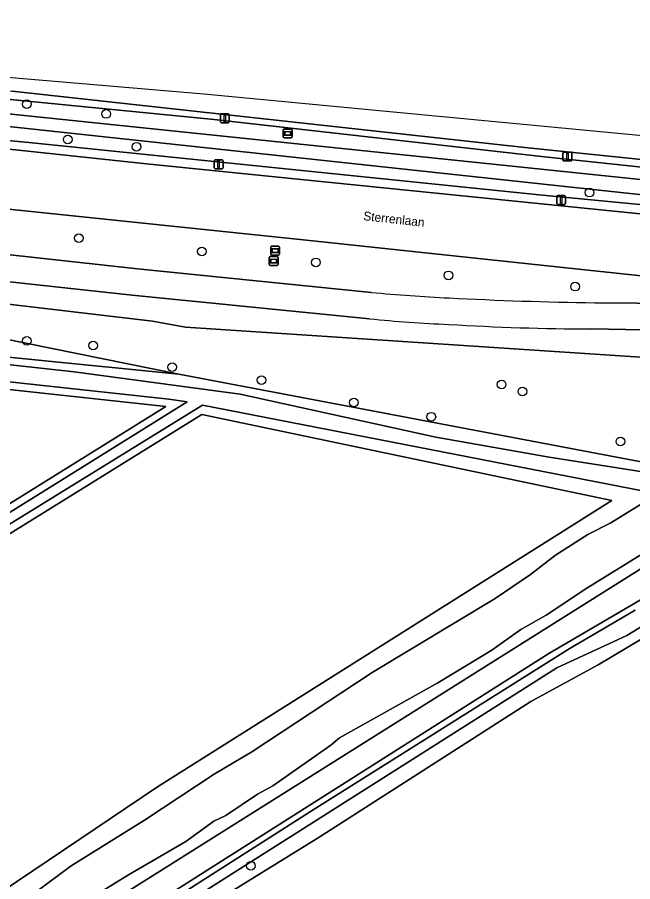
# Model space of a CAD drawing. Extents: x 162788 to 163838, y 385791 to 386523.
# Drawn here: x 163529.6 to 163598.9, y 386420.1 to 386517.4 of the extents above; entities that cross this region are included whole.
import ezdxf

# ---------------------------------------------------------------- set-up
doc = ezdxf.new("R2010")
doc.units = 0
for name, color, linetype in [('IMGEO_Berm_groen', 7, 'Continuous'), ('IMGEO_Boom', 7, 'Continuous'), ('IMGEO_Fietspad_gesloten', 7, 'Continuous'), ('IMGEO_Grasland_overig', 7, 'Continuous'), ('IMGEO_Groenvoorziening', 7, 'Continuous'), ('IMGEO_Informatiebord', 7, 'Continuous'), ('IMGEO_Lichtmast', 7, 'Continuous'), ('IMGEO_Loofbos', 7, 'Continuous'), ('IMGEO_Oever', 7, 'Continuous'), ('IMGEO_Openbare_ruimte_label', 7, 'Continuous'), ('IMGEO_OVBaan_gesloten', 7, 'Continuous'), ('IMGEO_Rijbaan_regionaal_gesloten', 7, 'Continuous'), ('IMGEO_Waterloop', 7, 'Continuous')]:
    doc.layers.add(name, color=color, linetype=linetype)

msp = doc.modelspace()

# ---------------------------------------------------------------- linework, layer by layer
at = {"layer": 'IMGEO_Berm_groen'}
for points in [[(163502.268, 386510.765), (163511.024, 386509.903), (163513.566, 386509.634), (163551.797, 386505.898)], [(163488.349, 386506.668), (163510.404, 386504.494), (163544.171, 386500.892), (163632.748, 386491.925), (163633.433, 386497.926), (163586.787, 386502.74), (163529.046, 386509.095)], [(163614.95, 386494.842), (163588.401, 386497.397), (163531.293, 386503.262), (163504.256, 386505.867)], [(163551.797, 386505.898), (163588.967, 386501.7), (163615.146, 386498.908)], [(163408.845, 386505.184), (163382.823, 386504.918), (163339.084, 386504.348), (163313.816, 386504.019), (163312.779, 386502.838), (163322.556, 386503.048), (163336.698, 386502.829), (163341.58, 386502.733), (163354.063, 386502.487), (163377.597, 386501.753), (163392.717, 386501.21), (163422.157, 386499.862), (163437.07, 386498.936), (163447.684, 386498.2), (163451.775, 386497.917), (163476.422, 386495.841), (163497.382, 386493.95), (163513.463, 386492.329), (163543.158, 386489.078), (163569.498, 386486.424)], [(163594.648, 386485.25), (163604.116, 386485.157), (163620.131, 386484.654), (163620.331, 386486.107), (163561.492, 386492.38), (163515.306, 386497.176)]]:
    msp.add_lwpolyline(points, dxfattribs=at)
for centre, radius, start, end in [((163587.435, 386675.239), 189.666, 264.57336, 267.22094), ((163602.356, 386962.857), 477.67, 267.10602, 269.07544)]:
    msp.add_arc(centre, radius, start, end, dxfattribs=at)
at = {"layer": 'IMGEO_Boom'}
for centre in [(163530.718, 386507.626), (163539.654, 386506.521), (163535.311, 386503.647), (163543.051, 386502.827), (163594.045, 386497.66), (163536.575, 386492.528), (163550.405, 386491.033), (163563.257, 386489.802), (163578.166, 386488.336), (163592.423, 386487.075), (163530.721, 386480.963), (163538.188, 386480.452), (163547.076, 386477.997), (163557.126, 386476.527), (163584.159, 386476.045), (163586.495, 386475.27), (163567.51, 386474.032), (163576.244, 386472.422), (163597.527, 386469.639), (163555.927, 386421.855)]:
    msp.add_circle(centre, 0.489, dxfattribs=at)
at = {"layer": 'IMGEO_Fietspad_gesloten'}
for points in [[(163476.422, 386495.841), (163451.775, 386497.917), (163447.684, 386498.2), (163447.558, 386495.135), (163476.013, 386493.062), (163496.644, 386491.109), (163542.581, 386486.123), (163569.285, 386483.446)], [(163569.498, 386486.424), (163543.158, 386489.078), (163513.463, 386492.329), (163497.382, 386493.95), (163476.422, 386495.841)], [(163620.346, 386481.447), (163637.893, 386479.866), (163646.607, 386478.939), (163644.408, 386482.109), (163620.131, 386484.654), (163604.116, 386485.157), (163594.648, 386485.25)], [(163594.227, 386482.314), (163603.992, 386482.133)]]:
    msp.add_lwpolyline(points, dxfattribs=at)
for centre, radius, start, end in [((163587.435, 386675.239), 189.666, 264.57336, 267.22094), ((163602.356, 386962.857), 477.67, 267.10602, 269.07544), ((163583.998, 386629.849), 147.141, 264.2612, 267.74985), ((163594.835, 386753.88), 271.567, 266.49257, 269.87174)]:
    msp.add_arc(centre, radius, start, end, dxfattribs=at)
at = {"layer": 'IMGEO_Grasland_overig'}
for points in [[(163609.972, 386461.674), (163530.606, 386411.736), (163508.344, 386398.609), (163502.97, 386394.804), (163500.738, 386394.072), (163499.305, 386392.84), (163498.074, 386392.291), (163497.125, 386391.868), (163496.628, 386391.81), (163494.388, 386391.549), (163468.576, 386408.683), (163466.904, 386409.785), (163463.499, 386412.323), (163460.871, 386414.287), (163452.188, 386431.166), (163452.353, 386431.82), (163452.585, 386432.415), (163452.967, 386432.905), (163451.764, 386435.791), (163426.74, 386484.123)], [(163689.349, 386265.559), (163554.317, 386352.369), (163530.224, 386368.614), (163500.811, 386388.481), (163501.915, 386389.741), (163502.813, 386390.765), (163508.757, 386394.537), (163589.476, 386445.759), (163600.071, 386451.949)]]:
    msp.add_lwpolyline(points, dxfattribs=at)
at = {"layer": 'IMGEO_Groenvoorziening'}
for points in [[(163496.644, 386491.109), (163476.013, 386493.062), (163447.558, 386495.135), (163436.207, 386495.962), (163421.921, 386496.877), (163416.565, 386497.119), (163416.729, 386495.064), (163447.481, 386493.27), (163467.054, 386491.699), (163487.006, 386489.37), (163500, 386488.248), (163507.278, 386487.619), (163544.863, 386483.183), (163548.582, 386482.522), (163613.437, 386478.233), (163623.373, 386477.329), (163632.55, 386476.266), (163639.446, 386472.523), (163647.005, 386478.019), (163647.317, 386477.986), (163646.607, 386478.939), (163637.893, 386479.866), (163620.346, 386481.447)], [(163613.437, 386478.233), (163548.582, 386482.522), (163544.863, 386483.183), (163507.278, 386487.619), (163500, 386488.248), (163487.006, 386489.37), (163467.054, 386491.699), (163447.481, 386493.27), (163416.729, 386495.064), (163416.941, 386492.397), (163430.626, 386491.16), (163447.119, 386489.171), (163500, 386483.982), (163527.829, 386481.252), (163547.829, 386477.218), (163603.437, 386466.663)], [(163569.285, 386483.446), (163542.581, 386486.123), (163496.644, 386491.109)], [(163603.992, 386482.133), (163594.227, 386482.314)]]:
    msp.add_lwpolyline(points, dxfattribs=at)
msp.add_lwpolyline([(163447.119, 386489.171), (163430.626, 386491.16), (163416.941, 386492.397), (163417.443, 386489.736), (163418.278, 386486.121), (163420.488, 386485.85), (163420.359, 386486.513), (163420.518, 386487.534), (163420.904, 386488.099), (163421.598, 386488.641), (163422.419, 386489.101), (163429.924, 386488.142), (163446.859, 386486.473), (163471.729, 386483.62), (163478.327, 386483.016), (163500, 386481.984), (163547.829, 386477.218), (163527.829, 386481.252), (163500, 386483.982)], close=True, dxfattribs=at)
for centre, radius, start, end in [((163583.998, 386629.849), 147.141, 264.2612, 267.74985), ((163594.835, 386753.88), 271.567, 266.49257, 269.87174)]:
    msp.add_arc(centre, radius, start, end, dxfattribs=at)
at = {"layer": 'IMGEO_Informatiebord'}
for p, q in [((163559.582, 386503.922), (163559.582, 386504.722)), ((163559.582, 386504.722), (163559.582, 386503.922)), ((163559.682, 386504.822), (163560.472, 386504.822)), ((163560.472, 386504.822), (163559.682, 386504.822)), ((163560.572, 386504.722), (163560.572, 386503.922)), ((163560.572, 386503.922), (163560.572, 386504.722)), ((163560.472, 386503.822), (163559.682, 386503.822)), ((163559.682, 386503.822), (163560.472, 386503.822)), ((163558.163, 386490.727), (163558.163, 386491.527)), ((163558.163, 386491.527), (163558.163, 386490.727)), ((163558.263, 386491.627), (163559.053, 386491.627)), ((163559.053, 386491.627), (163558.263, 386491.627)), ((163559.153, 386491.527), (163559.153, 386490.727)), ((163559.153, 386490.727), (163559.153, 386491.527)), ((163557.997, 386489.548), (163557.997, 386490.348)), ((163557.997, 386490.348), (163557.997, 386489.548)), ((163558.097, 386490.448), (163558.887, 386490.448)), ((163558.887, 386490.448), (163558.097, 386490.448)), ((163559.053, 386490.627), (163558.263, 386490.627)), ((163558.263, 386490.627), (163559.053, 386490.627)), ((163558.987, 386490.348), (163558.987, 386489.548)), ((163558.987, 386489.548), (163558.987, 386490.348)), ((163558.887, 386489.448), (163558.097, 386489.448)), ((163558.097, 386489.448), (163558.887, 386489.448))]:
    msp.add_line(p, q, dxfattribs=at)
for points in [[(163559.683, 386504.554), (163560.471, 386504.554), (163560.471, 386504.09), (163559.683, 386504.09), (163559.683, 386504.554)], [(163559.748, 386504.489), (163559.748, 386504.155), (163560.406, 386504.155), (163560.406, 386504.489), (163559.748, 386504.489)], [(163558.264, 386491.359), (163559.052, 386491.359), (163559.052, 386490.895), (163558.264, 386490.895), (163558.264, 386491.359)], [(163558.329, 386491.294), (163558.329, 386490.96), (163558.987, 386490.96), (163558.987, 386491.294), (163558.329, 386491.294)], [(163558.098, 386490.18), (163558.886, 386490.18), (163558.886, 386489.716), (163558.098, 386489.716), (163558.098, 386490.18)], [(163558.163, 386490.115), (163558.163, 386489.781), (163558.821, 386489.781), (163558.821, 386490.115), (163558.163, 386490.115)]]:
    msp.add_lwpolyline(points, dxfattribs=at)
for centre, start, end in [((163559.682, 386504.722), 90, 180), ((163559.682, 386504.722), 90, 180), ((163560.472, 386504.722), 0, 90), ((163560.472, 386504.722), 360, 90), ((163559.682, 386503.922), 180, 270), ((163559.682, 386503.922), 180, 270), ((163560.472, 386503.922), 270, 0), ((163560.472, 386503.922), 270, 0), ((163558.263, 386491.527), 90, 180), ((163558.263, 386491.527), 90, 180), ((163559.053, 386491.527), 0, 90), ((163559.053, 386491.527), 360, 90), ((163558.097, 386490.348), 90, 180), ((163558.097, 386490.348), 90, 180), ((163558.263, 386490.727), 180, 270), ((163558.263, 386490.727), 180, 270), ((163558.887, 386490.348), 0, 90), ((163558.887, 386490.348), 360, 90), ((163559.053, 386490.727), 270, 0), ((163559.053, 386490.727), 270, 0), ((163558.097, 386489.548), 180, 270), ((163558.097, 386489.548), 180, 270), ((163558.887, 386489.548), 270, 0), ((163558.887, 386489.548), 270, 0)]:
    msp.add_arc(centre, 0.1, start, end, dxfattribs=at)
at = {"layer": 'IMGEO_Lichtmast'}
for p, q in [((163552.505, 386505.618), (163552.505, 386506.418)), ((163552.505, 386506.418), (163552.505, 386505.618)), ((163552.605, 386506.518), (163553.395, 386506.518)), ((163553.395, 386506.518), (163552.605, 386506.518)), ((163553.495, 386506.418), (163553.495, 386505.618)), ((163553.495, 386505.618), (163553.495, 386506.418)), ((163553.395, 386505.518), (163552.605, 386505.518)), ((163552.605, 386505.518), (163553.395, 386505.518)), ((163591.064, 386501.327), (163591.064, 386502.127)), ((163591.064, 386502.127), (163591.064, 386501.327)), ((163591.164, 386502.227), (163591.954, 386502.227)), ((163591.954, 386502.227), (163591.164, 386502.227)), ((163592.054, 386502.127), (163592.054, 386501.327)), ((163592.054, 386501.327), (163592.054, 386502.127)), ((163551.803, 386500.446), (163551.803, 386501.246)), ((163551.803, 386501.246), (163551.803, 386500.446)), ((163551.903, 386501.346), (163552.693, 386501.346)), ((163552.693, 386501.346), (163551.903, 386501.346)), ((163552.793, 386501.246), (163552.793, 386500.446)), ((163552.793, 386500.446), (163552.793, 386501.246)), ((163591.954, 386501.227), (163591.164, 386501.227)), ((163591.164, 386501.227), (163591.954, 386501.227)), ((163552.693, 386500.346), (163551.903, 386500.346)), ((163551.903, 386500.346), (163552.693, 386500.346)), ((163590.362, 386496.431), (163590.362, 386497.231)), ((163590.362, 386497.231), (163590.362, 386496.431)), ((163590.462, 386497.331), (163591.252, 386497.331)), ((163591.252, 386497.331), (163590.462, 386497.331)), ((163591.352, 386497.231), (163591.352, 386496.431)), ((163591.352, 386496.431), (163591.352, 386497.231)), ((163591.252, 386496.331), (163590.462, 386496.331)), ((163590.462, 386496.331), (163591.252, 386496.331))]:
    msp.add_line(p, q, dxfattribs=at)
for points in [[(163552.925, 386506.393), (163553.075, 386506.393), (163553.075, 386505.643), (163552.925, 386505.643), (163552.925, 386506.393)], [(163591.484, 386502.102), (163591.634, 386502.102), (163591.634, 386501.352), (163591.484, 386501.352), (163591.484, 386502.102)], [(163552.223, 386501.221), (163552.373, 386501.221), (163552.373, 386500.471), (163552.223, 386500.471), (163552.223, 386501.221)], [(163590.782, 386497.206), (163590.932, 386497.206), (163590.932, 386496.456), (163590.782, 386496.456), (163590.782, 386497.206)]]:
    msp.add_lwpolyline(points, dxfattribs=at)
for centre, start, end in [((163552.605, 386506.418), 90, 180), ((163552.605, 386506.418), 90, 180), ((163553.395, 386506.418), 0, 90), ((163553.395, 386506.418), 360, 90), ((163552.605, 386505.618), 180, 270), ((163552.605, 386505.618), 180, 270), ((163553.395, 386505.618), 270, 0), ((163553.395, 386505.618), 270, 0), ((163591.164, 386502.127), 90, 180), ((163591.164, 386502.127), 90, 180), ((163591.954, 386502.127), 0, 90), ((163591.954, 386502.127), 360, 90), ((163551.903, 386501.246), 90, 180), ((163551.903, 386501.246), 90, 180), ((163552.693, 386501.246), 0, 90), ((163552.693, 386501.246), 360, 90), ((163591.164, 386501.327), 180, 270), ((163591.164, 386501.327), 180, 270), ((163591.954, 386501.327), 270, 0), ((163591.954, 386501.327), 270, 0), ((163551.903, 386500.446), 180, 270), ((163551.903, 386500.446), 180, 270), ((163552.693, 386500.446), 270, 0), ((163552.693, 386500.446), 270, 0), ((163590.462, 386497.231), 90, 180), ((163590.462, 386497.231), 90, 180), ((163591.252, 386497.231), 0, 90), ((163591.252, 386497.231), 360, 90), ((163590.462, 386496.431), 180, 270), ((163590.462, 386496.431), 180, 270), ((163591.252, 386496.431), 270, 0), ((163591.252, 386496.431), 270, 0)]:
    msp.add_arc(centre, 0.1, start, end, dxfattribs=at)
at = {"layer": 'IMGEO_Loofbos'}
for points in [[(163426.74, 386484.123), (163451.764, 386435.791), (163452.967, 386432.905), (163453.493, 386433.2), (163454.277, 386433.331), (163454.763, 386433.281), (163455.373, 386433.133), (163460.662, 386422.733), (163462.288, 386420.222), (163499.058, 386443.123), (163499.013, 386443.525), (163499.213, 386444.012), (163499.548, 386444.436), (163546.342, 386473.582), (163499.936, 386478.596), (163470.849, 386479.85), (163459.326, 386482.058), (163429.606, 386483.871), (163427.714, 386484.103)], [(163501.293, 386442.202), (163500.215, 386442.074), (163499.665, 386442.243), (163499.333, 386442.544), (163499.068, 386443.031), (163499.058, 386443.123), (163462.288, 386420.222), (163465.159, 386415.79), (163493.758, 386397.39), (163494.965, 386396.918), (163496.171, 386397.548), (163545.437, 386430.752), (163596.56, 386462.976), (163550.418, 386472.656)], [(163652.297, 386455.08), (163652.01, 386454.984), (163642, 386454.381), (163641.895, 386453.88), (163641.744, 386453.509), (163641.406, 386452.947), (163635.326, 386451.747), (163618.327, 386454.372), (163612.285, 386454.746), (163595.027, 386444.488), (163587.439, 386440.362), (163563.524, 386425.009), (163514.155, 386394.505), (163547.404, 386370.968), (163601.284, 386412.619), (163654.724, 386452.522)]]:
    msp.add_lwpolyline(points, close=True, dxfattribs=at)
at = {"layer": 'IMGEO_Oever'}
for points in [[(163615.146, 386498.908), (163588.967, 386501.7), (163551.797, 386505.898), (163513.566, 386509.634), (163513.422, 386508.12), (163615.315, 386497.535), (163615.459, 386497.337), (163615.598, 386497.094), (163615.668, 386496.895), (163615.704, 386496.649), (163615.654, 386496.299), (163615.595, 386496.16), (163615.444, 386495.958), (163615.291, 386495.853), (163614.998, 386495.783), (163513.293, 386506.772), (163513.151, 386505.276), (163510.537, 386505.541), (163510.703, 386507.032), (163471.698, 386510.651)], [(163504.256, 386505.867), (163531.293, 386503.262), (163588.401, 386497.397), (163614.95, 386494.842)], [(163603.437, 386466.663), (163547.829, 386477.218), (163500, 386481.984), (163478.327, 386483.016), (163471.729, 386483.62), (163446.859, 386486.473)], [(163465.904, 386483.746), (163475.78, 386481.703), (163480.455, 386481.543), (163484.096, 386481.842), (163488.086, 386481.494), (163491.228, 386481.195), (163497.214, 386481.494), (163500.406, 386480.846), (163505.444, 386480.746), (163512.926, 386479.749), (163518.586, 386479.401), (163536.043, 386477.458), (163554.725, 386474.954), (163576.744, 386470.114), (163589.513, 386467.871), (163609.831, 386464.665)], [(163531.749, 386418.914), (163535.708, 386421.831), (163543.966, 386426.985), (163551.785, 386432.179), (163556.044, 386434.697), (163569.583, 386443.607), (163583.42, 386451.957), (163587.42, 386454.654), (163590.219, 386456.832), (163593.879, 386459.149), (163596.438, 386460.488), (163601.757, 386463.744), (163550.47, 386473.729), (163500.488, 386442.918), (163500, 386443.71), (163548.758, 386474.079), (163546.68, 386474.406), (163500, 386479.449), (163470.948, 386480.702)], [(163470.849, 386479.85), (163499.936, 386478.596), (163546.342, 386473.582), (163499.548, 386444.436), (163499.213, 386444.012), (163499.013, 386443.525), (163499.058, 386443.123), (163499.068, 386443.031), (163499.333, 386442.544), (163499.665, 386442.243), (163500.215, 386442.074), (163501.293, 386442.202), (163550.418, 386472.656), (163596.56, 386462.976), (163545.437, 386430.752), (163496.171, 386397.548)], [(163530.606, 386411.736), (163609.972, 386461.674)], [(163602.775, 386458.705), (163593.757, 386453.112), (163589.178, 386450.055), (163586.318, 386448.457), (163583.039, 386446.119), (163576.96, 386442.463), (163565.901, 386436.251), (163564.941, 386435.412), (163558.402, 386430.857), (163556.663, 386429.898), (163553.103, 386427.521), (163551.744, 386426.862), (163548.604, 386424.564), (163542.145, 386420.809), (163530.787, 386413.817)], [(163601.284, 386412.619), (163547.404, 386370.968), (163541.102, 386366.096), (163506.006, 386388.716), (163505.593, 386389.215), (163514.155, 386394.505), (163563.524, 386425.009), (163587.439, 386440.362), (163595.027, 386444.488), (163612.285, 386454.746)], [(163600.071, 386451.949), (163589.476, 386445.759), (163508.757, 386394.537), (163502.813, 386390.765), (163501.915, 386389.741), (163500.811, 386388.481), (163530.224, 386368.614), (163554.317, 386352.369), (163689.349, 386265.559)], [(163606.486, 386452.796), (163598.256, 386447.763), (163590.383, 386444.149), (163513.194, 386395.185), (163510.448, 386393.443), (163504.97, 386389.968), (163503.825, 386389.082), (163503.752, 386388.569), (163504.229, 386388.24), (163506.467, 386387.03), (163541.772, 386364.331), (163546.997, 386369.285), (163547.347, 386369.562), (163548.312, 386370.325), (163552.581, 386373.702), (163561.428, 386380.287), (163590.981, 386402.973), (163605.796, 386414.557)], [(163638.788, 386299.111), (163571.441, 386342.562), (163502.351, 386388.086), (163502.145, 386388.378), (163502.028, 386388.687), (163502.068, 386389.016), (163502.236, 386389.334), (163502.375, 386389.496), (163502.766, 386389.782), (163503.068, 386389.935), (163562.953, 386428.155), (163591.761, 386446.29), (163599.189, 386450.65)]]:
    msp.add_lwpolyline(points, dxfattribs=at)
at = {"layer": 'IMGEO_OVBaan_gesloten'}
msp.add_lwpolyline([(163515.306, 386497.176), (163561.492, 386492.38), (163620.331, 386486.107), (163643.31, 386483.69), (163637.972, 386491.385), (163632.748, 386491.925), (163544.171, 386500.892), (163510.404, 386504.494), (163488.349, 386506.668)], dxfattribs=at)
at = {"layer": 'IMGEO_Rijbaan_regionaal_gesloten'}
for points in [[(163631.237, 386501.09), (163550.625, 386508.735), (163448.498, 386517.406), (163448.453, 386516.354)], [(163505.624, 386511.416), (163529.046, 386509.095), (163586.787, 386502.74), (163633.433, 386497.926), (163631.237, 386501.09)]]:
    msp.add_lwpolyline(points, dxfattribs=at)
at = {"layer": 'IMGEO_Waterloop'}
msp.add_lwpolyline([(163513.422, 386508.12), (163513.293, 386506.772), (163614.998, 386495.783), (163615.291, 386495.853), (163615.444, 386495.958), (163615.595, 386496.16), (163615.654, 386496.299), (163615.704, 386496.649), (163615.668, 386496.895), (163615.598, 386497.094), (163615.459, 386497.337), (163615.315, 386497.535)], close=True, dxfattribs=at)
for points in [[(163609.831, 386464.665), (163589.513, 386467.871), (163576.744, 386470.114), (163554.725, 386474.954), (163536.043, 386477.458), (163518.586, 386479.401), (163512.926, 386479.749), (163505.444, 386480.746), (163500.406, 386480.846), (163497.214, 386481.494), (163491.228, 386481.195), (163488.086, 386481.494), (163484.096, 386481.842), (163480.455, 386481.543), (163475.78, 386481.703), (163465.904, 386483.746)], [(163470.948, 386480.702), (163500, 386479.449), (163546.68, 386474.406), (163548.758, 386474.079), (163500, 386443.71), (163500.488, 386442.918), (163550.47, 386473.729), (163601.757, 386463.744), (163596.438, 386460.488), (163593.879, 386459.149), (163590.219, 386456.832), (163587.42, 386454.654), (163583.42, 386451.957), (163569.583, 386443.607), (163556.044, 386434.697), (163551.785, 386432.179), (163543.966, 386426.985), (163535.708, 386421.831), (163531.749, 386418.914)], [(163530.787, 386413.817), (163542.145, 386420.809), (163548.604, 386424.564), (163551.744, 386426.862), (163553.103, 386427.521), (163556.663, 386429.898), (163558.402, 386430.857), (163564.941, 386435.412), (163565.901, 386436.251), (163576.96, 386442.463), (163583.039, 386446.119), (163586.318, 386448.457), (163589.178, 386450.055), (163593.757, 386453.112), (163602.775, 386458.705)], [(163605.796, 386414.557), (163590.981, 386402.973), (163561.428, 386380.287), (163552.581, 386373.702), (163548.312, 386370.325), (163547.347, 386369.562), (163546.997, 386369.285), (163541.772, 386364.331), (163506.467, 386387.03), (163504.229, 386388.24), (163503.752, 386388.569), (163503.825, 386389.082), (163504.97, 386389.968), (163510.448, 386393.443), (163513.194, 386395.185), (163590.383, 386444.149), (163598.256, 386447.763), (163606.486, 386452.796)], [(163599.189, 386450.65), (163591.761, 386446.29), (163562.953, 386428.155), (163503.068, 386389.935), (163502.766, 386389.782), (163502.375, 386389.496), (163502.236, 386389.334), (163502.068, 386389.016), (163502.028, 386388.687), (163502.145, 386388.378), (163502.351, 386388.086), (163571.441, 386342.562), (163638.788, 386299.111)]]:
    msp.add_lwpolyline(points, dxfattribs=at)

# ---------------------------------------------------------------- texts
at = {"layer": 'IMGEO_Openbare_ruimte_label'}
msp.add_text('Sterrenlaan', height=1, rotation=353.68512, dxfattribs=at).set_placement((163568.554, 386494.561))

doc.saveas('drawing.dxf')
